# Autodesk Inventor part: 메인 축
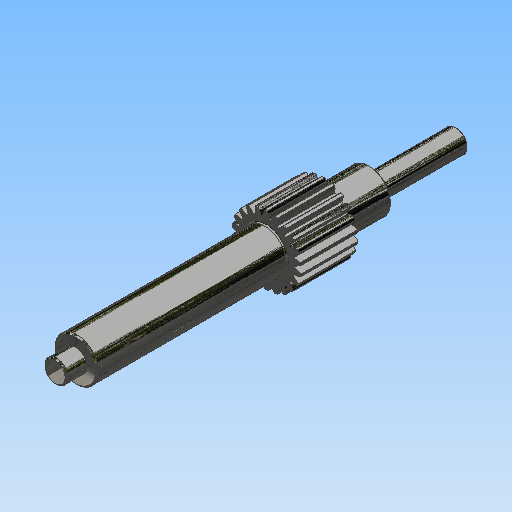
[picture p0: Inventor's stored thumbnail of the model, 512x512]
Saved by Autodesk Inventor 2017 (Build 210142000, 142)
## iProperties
Created: 2016-02
Part Number: 메인 축
Material: 강철, 연강
Document SubType Name: Modeling
Categories: <?xml version="1.0" encoding="UTF-16"?> <MemberInstance><Categories><FamilyTemplate><FamilyTemplateParameter ValueType="xs:double" Id="1" ObjectReferenceKey="da
Density: 7.86 g/cm^3
Mass: 187.503 g
Surface Area: 82.0529 cm^2
Volume: 23.8554 cm^3
Appearance: 강철 - 광택
Author: mdu
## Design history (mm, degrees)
sketch "Sketch1"
  geometry: C1 r 12 at (0, 0)
  constraints: 1 centre point
  dimensions: "d0" = 24 diameter of C1 (= da_da)
extrude "Extrusion1" new body sketch "Sketch1" distance "d1" = 20 (= da_b); taper "d2" = 0 deg
workplane "Work Plane2"
feature "피치 지름" dims "d4" = 10, "d5" = 0
workplane "Work Plane8"
workplane "Work Plane9"
chamfer "모따기1" distance "d49" = 0.2; stored, may be unused: second distance "d50" = 2, angle "d51" = 45 deg
sketch "스케치3"
  geometry: C1 r 7.5 at (0, 0); 1 further point
  constraints: 1 centre point, 1 coincident
  dimensions: "d52" = 15 diameter of C1
extrude "돌출2" join sketch "스케치3" distance "d53" = 66; taper "d54" = 0 deg
sketch "스케치4"
  geometry: C1 r 4 at (0, 0); 1 further point
  constraints: 1 centre point, 1 coincident
  dimensions: "d55" = 8 diameter of C1
extrude "돌출3" join sketch "스케치4" distance "d56" = 7; taper "d57" = 0 deg
sketch "스케치5"
  geometry: C1 r 7.5 at (0, 0) reference; C2 r 7.5 at (0, 0) reference; 1 further point
extrude "돌출4" join sketch "스케치5" distance "d62" = 16; taper "d63" = 0 deg
sketch "스케치6"
  geometry: C1 r 4 at (0, 0); 1 further point
  constraints: 1 centre point, 1 coincident
  dimensions: "d64" = 8 diameter of C1
extrude "돌출5" join sketch "스케치6" distance "d65" = 30; taper "d66" = 0 deg
chamfer "모따기2" distance "d58" = 0.5; stored, may be unused: second distance "d59" = 2, angle "d60" = 45 deg
fillet "모깎기1" dims "d61" = 0.5
feature "스퍼 기어" dims "d39" = 0, "d61" = 0.5, "da_b" = 20, "da_d" = 22, "da_aw" = 31, "da_da" = 24, "da_df" = 19.5, "da_dw" = 22, angle "da_beta" = 0 deg, "da_lefttooth" = 0, "da_righttooth" = 0
sketch "스케치7" dims "d68" = 18
  geometry: C1 r 0.25 at (0, -9); 2 further points
  constraints: 2 vertical alignment, 1 centre point, 1 coincident, 2 other
  dimensions: "d67" = 0.5 diameter of C1
extrude "돌출6" join sketch "스케치7" distance "d69" = 0.3; taper "d70" = 0 deg
body "Solid1"
sketch "Sketch2"
  geometry: C1 r 12 at (0, 0) reference; C2 r 11 at (0, 0)
  constraints: 1 centre point, 1 coincident
  dimensions: "d3" = 22 diameter of C2 (= da_dw)
body "Srf1"
node "투영된 루프1"
other parameters: "d16" = 31 (= da_aw), "d17" = 0, "d34" = 1.428 (computed from da_z), "d41" = 0, "d43" = 31 (= da_aw), "d46" = 31 (= da_aw), "d47" = 0, "d48" = 0
